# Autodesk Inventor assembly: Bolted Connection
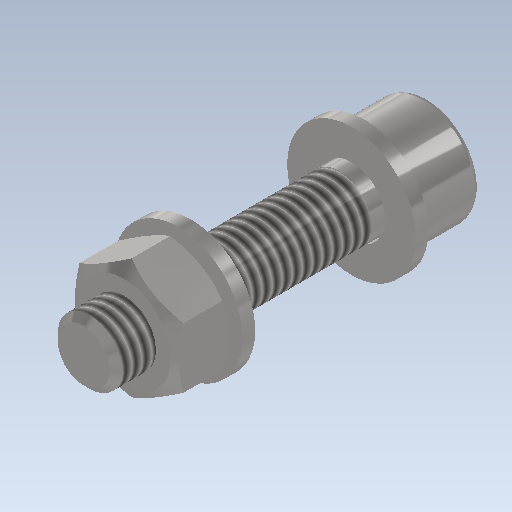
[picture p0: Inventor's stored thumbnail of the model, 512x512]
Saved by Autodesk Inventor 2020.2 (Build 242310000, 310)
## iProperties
ClientObjectVersion: 1
Created: 2020-01
Part Number: Bolted Connection
Document SubType Name: Assembly
Designer: thira
Mass: 29.971 g
Surface Area: 29.8218 cm^2
Volume: 3.8522 cm^3
Density: 7.78025 g/cm^3
Author: thira
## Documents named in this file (4)
- C:\Users\thira\OneDrive\เดสก์ท็อป\INV-01 Intro to Modeling_2020\Wheel Assem Final V1\Wheel Assy_Joint\Design Accelerator\Bolted Connection1.iam
- C:\Users\thira\OneDrive\เอกสาร\Inventor\Content Center Files\R2020\en-US\ISO 7089\ISO 7089 - 8 - 140 HV(1).ipt
- C:\Users\thira\OneDrive\เอกสาร\Inventor\Content Center Files\R2020\en-US\ISO 4762(2)\ISO 4762 - M8 x 35ISO.ipt
- C:\Users\thira\OneDrive\เอกสาร\Inventor\Content Center Files\R2020\en-US\ISO 4032(2)\ISO 4032 - M8 - ISO.ipt
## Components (4 placed, 3 different names)
1. ISO 7089 8:1
2. ISO 4762 M8 x 35:1
3. ISO 7089 8:2
4. ISO 4032 M8:1
